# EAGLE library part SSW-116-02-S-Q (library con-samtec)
THROUGH-HOLE .025" SQ POST SOCKET Source: Samtec SSW.pdf
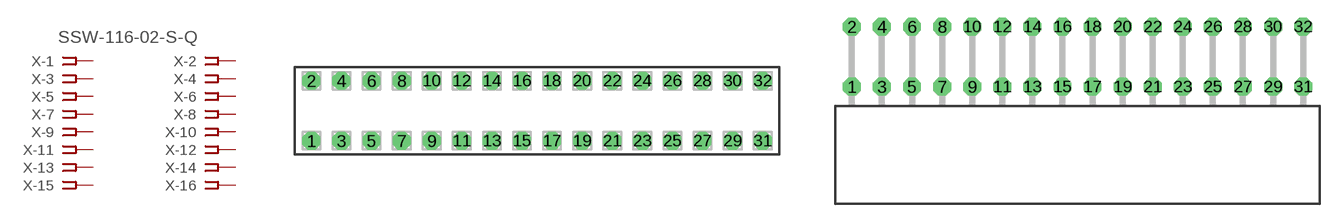
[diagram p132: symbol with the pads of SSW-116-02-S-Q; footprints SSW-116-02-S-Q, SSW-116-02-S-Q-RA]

Designator prefix X; gates -1=FPINV -2=FPIN -3=FPIN -4=FPIN -5=FPIN -6=FPIN -7=FPIN -8=FPIN -9=FPIN -10=FPIN -11=FPIN -12=FPIN -13=FPIN -14=FPIN -15=FPIN -16=FPIN -17=FPIN -18=FPIN -19=FPIN -20=FPIN -21=FPIN -22=FPIN -23=FPIN -24=FPIN -25=FPIN -26=FPIN -27=FPIN -28=FPIN -29=FPIN -30=FPIN -31=FPIN -32=FPIN

## SSW-116-02-S-Q (OC_FARNELL: unknown; OC_NEWARK: unknown)  [SSW-116-02-S-Q]
1  -1:1  pas
2  -2:1  pas
3  -3:1  pas
4  -4:1  pas
5  -5:1  pas
6  -6:1  pas
7  -7:1  pas
8  -8:1  pas
9  -9:1  pas
10  -10:1  pas
11  -11:1  pas
12  -12:1  pas
13  -13:1  pas
14  -14:1  pas
15  -15:1  pas
16  -16:1  pas
17  -17:1  pas
18  -18:1  pas
19  -19:1  pas
20  -20:1  pas
21  -21:1  pas
22  -22:1  pas
23  -23:1  pas
24  -24:1  pas
25  -25:1  pas
26  -26:1  pas
27  -27:1  pas
28  -28:1  pas
29  -29:1  pas
30  -30:1  pas
31  -31:1  pas
32  -32:1  pas

## SSW-116-02-S-QRA (OC_FARNELL: unknown; OC_NEWARK: unknown)  [SSW-116-02-S-Q-RA]
Pads as for SSW-116-02-S-Q

## Footprint SSW-116-02-S-Q (pad centres in mm)
THROUGH-HOLE .025" SQ POST SOCKET Source: Samtec SSW.pdf
drill 1 pad 1.5 octagon: 1 -19.05,-2.54; 2 -19.05,2.54; 3 -16.51,-2.54; 4 -16.51,2.54; 5 -13.97,-2.54; 6 -13.97,2.54; 7 -11.43,-2.54; 8 -11.43,2.54; 9 -8.89,-2.54; 10 -8.89,2.54; 11 -6.35,-2.54; 12 -6.35,2.54; 13 -3.81,-2.54; 14 -3.81,2.54; 15 -1.27,-2.54; 16 -1.27,2.54; 17 1.27,-2.54; 18 1.27,2.54; 19 3.81,-2.54; 20 3.81,2.54; 21 6.35,-2.54; 22 6.35,2.54; 23 8.89,-2.54; 24 8.89,2.54; 25 11.43,-2.54; 26 11.43,2.54; 27 13.97,-2.54; 28 13.97,2.54; 29 16.51,-2.54; 30 16.51,2.54; 31 19.05,-2.54; 32 19.05,2.54

## Footprint SSW-116-02-S-Q-RA (pad centres in mm)
THROUGH-HOLE .025" SQ POST SOCKET Source: Samtec SSW.pdf
drill 1 pad 1.5 octagon: 1 -19.05,1.524; 2 -19.05,6.604; 3 -16.51,1.524; 4 -16.51,6.604; 5 -13.97,1.524; 6 -13.97,6.604; 7 -11.43,1.524; 8 -11.43,6.604; 9 -8.89,1.524; 10 -8.89,6.604; 11 -6.35,1.524; 12 -6.35,6.604; 13 -3.81,1.524; 14 -3.81,6.604; 15 -1.27,1.524; 16 -1.27,6.604; 17 1.27,1.524; 18 1.27,6.604; 19 3.81,1.524; 20 3.81,6.604; 21 6.35,1.524; 22 6.35,6.604; 23 8.89,1.524; 24 8.89,6.604; 25 11.43,1.524; 26 11.43,6.604; 27 13.97,1.524; 28 13.97,6.604; 29 16.51,1.524; 30 16.51,6.604; 31 19.05,1.524; 32 19.05,6.604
